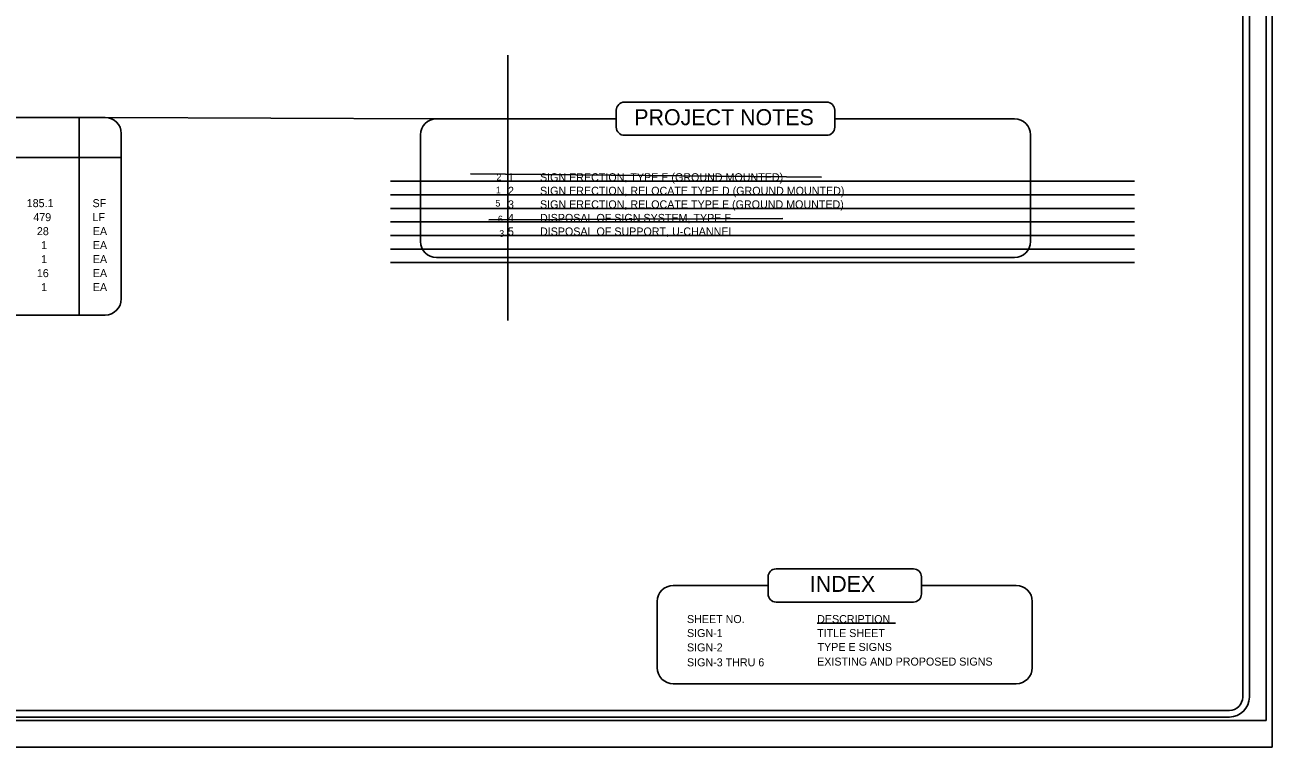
# Model space of a CAD drawing. Extents: x 2046816 to 2049224, y 578750 to 586986.
# Drawn here: x 2048289 to 2049224, y 585891 to 586432 of the extents above; entities that cross this region are included whole.
import ezdxf

# ---------------------------------------------------------------- set-up
doc = ezdxf.new("R2010")
doc.units = 0
for name, color, linetype in [('Default', 7, 'Continuous'), ('Scratch_Level_2', 7, 'Continuous'), ('Scratch_Level_3', 7, 'Continuous'), ('Scratch_Level_5', 7, 'Continuous'), ('Sheet Plot Border Inside CELL', 7, 'Continuous'), ('Sheet Plot Border Outside CELL', 7, 'Continuous'), ('Sheet Title CELL', 7, 'Continuous')]:
    doc.layers.add(name, color=color, linetype=linetype)

msp = doc.modelspace()

# ---------------------------------------------------------------- linework, layer by layer
at = {"layer": 'Default'}
for p, q in [((2048329.89, 586362.96), (2048329.89, 586214.83)), ((2047904.15, 586332.97), (2048361.44, 586332.97)), ((2048883.11, 585983.8), (2048941.86, 585983.8))]:
    msp.add_line(p, q, dxfattribs=at)
at = {"layer": 'Scratch_Level_2'}
for p, q in [((2048651.34, 586409.77), (2048651.34, 586210.79)), ((2048563.2, 586315.14), (2049121.11, 586315.14)), ((2048563.2, 586304.98), (2049121.11, 586304.98)), ((2048563.2, 586294.81), (2049121.11, 586294.81)), ((2048563.2, 586284.64), (2049121.11, 586284.64)), ((2048563.2, 586274.47), (2049121.11, 586274.47)), ((2048563.2, 586264.3), (2049121.11, 586264.3)), ((2048563.2, 586254.14), (2049121.11, 586254.14))]:
    msp.add_line(p, q, dxfattribs=at)
at = {"layer": 'Scratch_Level_3'}
for p, q in [((2048623.17, 586320.77), (2048886.35, 586318.2)), ((2048637.06, 586286.21), (2048857.29, 586287.17))]:
    msp.add_line(p, q, dxfattribs=at)
at = {"layer": 'Scratch_Level_5'}
msp.add_line((2048349.44, 586362.96), (2048597.78, 586362.01), dxfattribs=at)
at = {"layer": 'Sheet Plot Border Inside CELL'}
msp.add_lwpolyline([(2047553.67, 585910.81), (2049219.66, 585910.81), (2049219.66, 586965.81), (2047553.67, 586965.81)], close=True, dxfattribs=at)
at = {"layer": 'Sheet Plot Border Outside CELL'}
msp.add_lwpolyline([(2049224.17, 586985.81), (2047540.67, 586985.81), (2047540.67, 585890.81), (2049224.17, 585890.81)], close=True, dxfattribs=at)
at = {"layer": 'Sheet Title CELL'}
for p, q in [((2048738.57, 586374.44), (2048890.28, 586374.44)), ((2048259.96, 586362.96), (2048349.44, 586362.96)), ((2048597.78, 586362.01), (2048732.57, 586362.01)), ((2048732.57, 586368.44), (2048732.57, 586355.58)), ((2048896.28, 586368.44), (2048896.28, 586355.58)), ((2048896.28, 586362.01), (2049031.07, 586362.01)), ((2048361.44, 586350.96), (2048361.44, 586226.83)), ((2048585.78, 586350.01), (2048585.78, 586269.99)), ((2048890.28, 586349.58), (2048738.57, 586349.58)), ((2049043.07, 586350.01), (2049043.07, 586269.99)), ((2048597.78, 586257.99), (2049031.07, 586257.99)), ((2047916.15, 586214.83), (2048349.44, 586214.83)), ((2048846.35, 586018.43), (2048846.35, 586005.58)), ((2048852.35, 586024.43), (2048955.32, 586024.43)), ((2048961.32, 586018.43), (2048961.32, 586005.58)), ((2048775.25, 586012.01), (2048846.35, 586012.01)), ((2049032.41, 586012.01), (2048961.32, 586012.01)), ((2048763.25, 586000.01), (2048763.25, 585950.32)), ((2048955.32, 585999.58), (2048852.35, 585999.58)), ((2049044.41, 586000.01), (2049044.41, 585950.32)), ((2049032.41, 585938.32), (2048775.25, 585938.32)), ((2047772.18, 585918.31), (2049192.16, 585918.31))]:
    msp.add_line(p, q, dxfattribs=at)
for points in [[(2049202.16, 585928.31), (2049202.16, 586948.31)], [(2049207.16, 585928.31), (2049207.16, 586948.31)], [(2047722.16, 585913.31), (2049192.16, 585913.31)]]:
    msp.add_lwpolyline(points, dxfattribs=at)
for centre, radius, start, end in [((2048738.57, 586368.44), 6, 90, 180), ((2048890.28, 586368.44), 6, 360, 90), ((2048349.44, 586350.96), 12, 0, 90), ((2048597.78, 586350.01), 12, 90, 180), ((2049031.07, 586350.01), 12, 360, 90), ((2048738.57, 586355.58), 6, 180, 270), ((2048890.28, 586355.58), 6, 270, 0), ((2048597.78, 586269.99), 12, 180, 270), ((2049031.07, 586269.99), 12, 270, 0), ((2048349.44, 586226.83), 12, 270, 360), ((2048852.35, 586018.43), 6, 90, 180), ((2048955.32, 586018.43), 6, 360, 90), ((2048775.25, 586000.01), 12, 90, 180), ((2049032.41, 586000.01), 12, 360, 90), ((2048852.35, 586005.58), 6, 180, 270), ((2048955.32, 586005.58), 6, 270, 0), ((2048775.25, 585950.32), 12, 180, 270), ((2049032.41, 585950.32), 12, 270, 0), ((2049192.16, 585928.31), 15, 270, 0), ((2049192.16, 585928.31), 10, 270, 0)]:
    msp.add_arc(centre, radius, start, end, dxfattribs=at)

# ---------------------------------------------------------------- texts
at = {"layer": 'Default'}
for s, height, p in [('PROJECT NOTES', 12, (2048746.01, 586357.19)), ('1', 6, (2048651.34, 586315.14)), ('SIGN ERECTION, TYPE E (GROUND MOUNTED)', 6, (2048675.34, 586315.14)), ('2', 6, (2048651.34, 586304.98)), ('SIGN ERECTION, RELOCATE TYPE D (GROUND MOUNTED)', 6, (2048675.34, 586304.98)), ('185.1', 6, (2048290.54, 586295.7)), ('SF', 6, (2048339.89, 586295.7)), ('3', 6, (2048651.34, 586294.81)), ('SIGN ERECTION, RELOCATE TYPE E (GROUND MOUNTED)', 6, (2048675.34, 586294.81)), ('479', 6, (2048295.48, 586285.2)), ('LF', 6, (2048339.89, 586285.2)), ('4', 6, (2048651.34, 586284.64)), ('DISPOSAL OF SIGN SYSTEM, TYPE E', 6, (2048675.34, 586284.64)), ('28', 6, (2048298.16, 586274.71)), ('EA', 6, (2048340.1, 586274.71)), ('5', 6, (2048651.34, 586274.47)), ('DISPOSAL OF SUPPORT, U-CHANNEL', 6, (2048675.34, 586274.47)), ('1', 6, (2048301.34, 586264.21)), ('EA', 6, (2048340.1, 586264.21)), ('1', 6, (2048301.34, 586253.71)), ('EA', 6, (2048340.1, 586253.71)), ('16', 6, (2048298.14, 586243.21)), ('EA', 6, (2048340.1, 586243.21)), ('1', 6, (2048301.34, 586232.72)), ('EA', 6, (2048340.1, 586232.72)), ('INDEX', 12, (2048877.62, 586007.19)), ('SHEET NO.', 6, (2048785.54, 585983.8)), ('DESCRIPTION', 6, (2048883.11, 585983.8)), ('SIGN-1', 6, (2048785.54, 585973.3)), ('TITLE SHEET', 6, (2048883.11, 585973.3)), ('SIGN-2', 6, (2048785.54, 585962.54)), ('TYPE E SIGNS', 6, (2048883.43, 585962.88)), ('SIGN-3 THRU 6', 6, (2048785.54, 585951.37)), ('EXISTING AND PROPOSED SIGNS', 6, (2048883.11, 585951.91))]:
    msp.add_text(s, height=height, dxfattribs=at).set_placement(p)
at = {"layer": 'Scratch_Level_5'}
for s, p in [('2', (2048642.65, 586315.7)), ('1', (2048642.32, 586306.11)), ('5', (2048641.89, 586296.15)), ('6', (2048643.79, 586284.27)), ('3', (2048644.79, 586273.49))]:
    msp.add_text(s, height=5, dxfattribs=at).set_placement(p)

doc.saveas('drawing.dxf')
